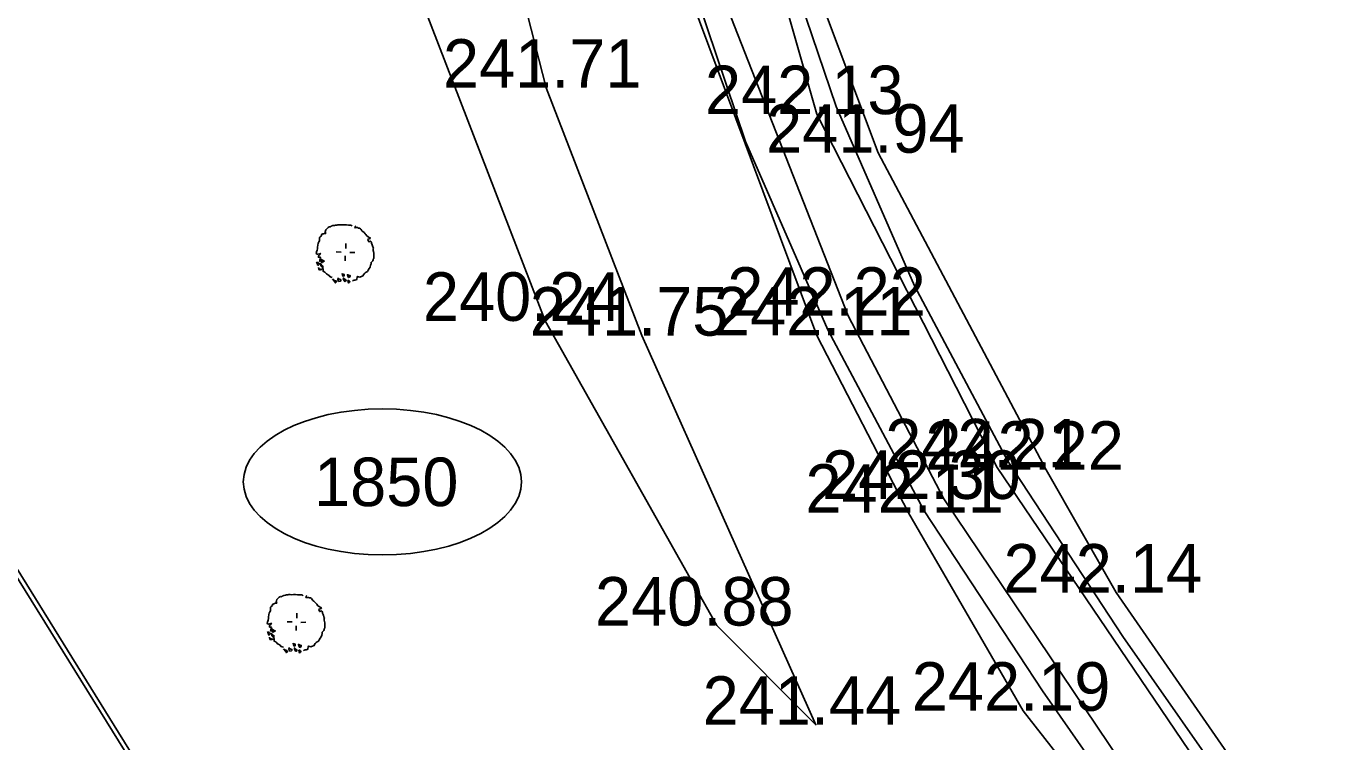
# Model space of a CAD drawing. Extents: x -601754 to -601440, y -1201912 to -1200862.
# Drawn here: x -601535.5 to -601481.8, y -1201665.6 to -1201636.1 of the extents above; entities that cross this region are included whole.
import ezdxf

# ---------------------------------------------------------------- set-up
doc = ezdxf.new("R2010")
doc.units = 0
for name, color, linetype in [('Hranice parcel', 7, 'Continuous'), ('Parcelní čísla', 7, 'Continuous'), ('u_dotčené parcely', 7, 'Continuous'), ('u_hrany', 7, 'Continuous'), ('u_vysadba', 7, 'Continuous'), ('u_vyska', 7, 'Continuous')]:
    doc.layers.add(name, color=color, linetype=linetype)

msp = doc.modelspace()

# ---------------------------------------------------------------- linework, layer by layer
at = {"layer": 'Hranice parcel'}
for points in [[(-601518.5, -1201574.62), (-601510.22, -1201581.07), (-601510.94, -1201612.53), (-601510.72, -1201619.53), (-601510.05, -1201624.75), (-601508.24, -1201633.75), (-601505.86, -1201640.82), (-601502.47, -1201648.58), (-601498.5, -1201656.04), (-601493.62, -1201663.46), (-601488.75, -1201670.45), (-601479.72, -1201682.69), (-601461.88, -1201705.09), (-601454.585, -1201713.629)], [(-601482.011, -1201718.681), (-601492.39, -1201715.61), (-601519.73, -1201684.8), (-601540.64, -1201651.14), (-601563.05, -1201608.38), (-601567.44, -1201599.25)], [(-601460.43, -1201700.48), (-601476.54, -1201680.26), (-601485.5, -1201668.12), (-601490.31, -1201661.22), (-601495.06, -1201653.99), (-601498.9, -1201646.76), (-601502.13, -1201639.37), (-601504.35, -1201632.81), (-601505.66, -1201626.3)]]:
    msp.add_lwpolyline(points, dxfattribs=at)
at = {"layer": 'u_dotčené parcely'}
msp.add_ellipse((-601520.821, -1201654.846), major_axis=(-5.732, 0), ratio=0.524694, dxfattribs=at)
at = {"layer": 'u_hrany'}
for points in [[(-601514.2, -1201569.51), (-601517.03, -1201570.93), (-601522.49, -1201584.67), (-601523.6, -1201596.8), (-601523.78, -1201607.28), (-601522.35, -1201622.38), (-601520.26, -1201632.29), (-601514.11, -1201648.21), (-601507.05, -1201660.77), (-601502.96, -1201664.86), (-601510.13, -1201648.82), (-601514.08, -1201638.6), (-601517, -1201627.14), (-601517.98, -1201618.06), (-601518.55, -1201594.5), (-601514.93, -1201583.59), (-601509.76, -1201580.82)], [(-601567.51, -1201596.21), (-601562.55, -1201607.8), (-601549.33, -1201634.79), (-601540.29, -1201651.32), (-601519.62, -1201684.67)], [(-601460.33, -1201700.35), (-601477.02, -1201679.01), (-601490.59, -1201659.41), (-601493.47, -1201654.35), (-601500.4, -1201641.28), (-601502.56, -1201635.52), (-601504.77, -1201626.02), (-601500.77, -1201618.77)], [(-601454.585, -1201708.29), (-601460.41, -1201701.5), (-601476.94, -1201680.56), (-601485.91, -1201668.41), (-601495.49, -1201654.25), (-601502.92, -1201639.69), (-601504.84, -1201632.93)], [(-601502.92, -1201648.81), (-601508.49, -1201633.89)], [(-601507.17, -1201633.88), (-601501.63, -1201648), (-601497.69, -1201655.55), (-601488, -1201669.96), (-601478.86, -1201682.08), (-601462.72, -1201703.16), (-601454.585, -1201712.627)], [(-601502.92, -1201648.81), (-601499.15, -1201656.12), (-601494.42, -1201664.28), (-601479.96, -1201682.77)]]:
    msp.add_lwpolyline(points, dxfattribs=at)
at = {"layer": 'u_vysadba'}
for points in [[(-601523.335, -1201644.685), (-601523.333, -1201644.656), (-601523.273, -1201644.63), (-601523.243, -1201644.617), (-601523.213, -1201644.604), (-601523.184, -1201644.605), (-601523.155, -1201644.607), (-601523.168, -1201644.577), (-601523.181, -1201644.547), (-601523.164, -1201644.504), (-601523.147, -1201644.461), (-601523.116, -1201644.418), (-601523.085, -1201644.391), (-601523.054, -1201644.363), (-601523.009, -1201644.336), (-601522.965, -1201644.338), (-601522.934, -1201644.311), (-601522.86, -1201644.285), (-601522.801, -1201644.274), (-601522.756, -1201644.262), (-601522.698, -1201644.265), (-601522.653, -1201644.252), (-601522.609, -1201644.255), (-601522.536, -1201644.259), (-601522.463, -1201644.248), (-601522.39, -1201644.252), (-601522.302, -1201644.256), (-601522.214, -1201644.261), (-601522.141, -1201644.265), (-601522.098, -1201644.282), (-601522.07, -1201644.298)], [(-601521.923, -1201644.291), (-601521.939, -1201644.319), (-601521.941, -1201644.349), (-601521.957, -1201644.377), (-601521.912, -1201644.365), (-601521.883, -1201644.366), (-601521.854, -1201644.368), (-601521.811, -1201644.385), (-601521.767, -1201644.387), (-601521.725, -1201644.419), (-601521.697, -1201644.449), (-601521.67, -1201644.495), (-601521.628, -1201644.526), (-601521.572, -1201644.573), (-601521.53, -1201644.619), (-601521.503, -1201644.65), (-601521.462, -1201644.711), (-601521.405, -1201644.743), (-601521.363, -1201644.775), (-601521.32, -1201644.791), (-601521.321, -1201644.821)], [(-601523.335, -1201644.685), (-601523.336, -1201644.7), (-601523.382, -1201644.741), (-601523.413, -1201644.769), (-601523.415, -1201644.813), (-601523.417, -1201644.856), (-601523.42, -1201644.915), (-601523.437, -1201644.958), (-601523.453, -1201644.986), (-601523.469, -1201645.015), (-601523.487, -1201645.072), (-601523.489, -1201645.102), (-601523.492, -1201645.16), (-601523.494, -1201645.204), (-601523.496, -1201645.233), (-601523.514, -1201645.305), (-601523.531, -1201645.348), (-601523.533, -1201645.392), (-601523.549, -1201645.42), (-601523.536, -1201645.45), (-601523.493, -1201645.467), (-601523.404, -1201645.443), (-601523.374, -1201645.43), (-601523.407, -1201645.487), (-601523.437, -1201645.514), (-601523.453, -1201645.543), (-601523.456, -1201645.586), (-601523.427, -1201645.588), (-601523.383, -1201645.59), (-601523.37, -1201645.62), (-601523.387, -1201645.663), (-601523.403, -1201645.692), (-601523.405, -1201645.736), (-601523.407, -1201645.779)], [(-601521.321, -1201644.821), (-601521.366, -1201644.833), (-601521.411, -1201644.845), (-601521.427, -1201644.874), (-601521.414, -1201644.904), (-601521.387, -1201644.949), (-601521.357, -1201644.936), (-601521.312, -1201644.924), (-601521.284, -1201644.954), (-601521.271, -1201644.984), (-601521.273, -1201645.014), (-601521.247, -1201645.074), (-601521.235, -1201645.118), (-601521.222, -1201645.163), (-601521.195, -1201645.208), (-601521.197, -1201645.237), (-601521.199, -1201645.281), (-601521.201, -1201645.31), (-601521.189, -1201645.355), (-601521.177, -1201645.414), (-601521.18, -1201645.472), (-601521.169, -1201645.532), (-601521.17, -1201645.561), (-601521.172, -1201645.59), (-601521.174, -1201645.634), (-601521.205, -1201645.661), (-601521.206, -1201645.691), (-601521.223, -1201645.734), (-601521.239, -1201645.762), (-601521.285, -1201645.804), (-601521.289, -1201645.862), (-601521.306, -1201645.92), (-601521.325, -1201645.992), (-601521.372, -1201646.048), (-601521.405, -1201646.119), (-601521.437, -1201646.176), (-601521.497, -1201646.202), (-601521.528, -1201646.23), (-601521.574, -1201646.272), (-601521.605, -1201646.314), (-601521.622, -1201646.357), (-601521.682, -1201646.383), (-601521.727, -1201646.395), (-601521.757, -1201646.408), (-601521.8, -1201646.391), (-601521.843, -1201646.375), (-601521.86, -1201646.418), (-601521.877, -1201646.475), (-601521.894, -1201646.518), (-601521.939, -1201646.531), (-601521.983, -1201646.528)], [(-601522.519, -1201645.378), (-601522.724, -1201645.367)], [(-601522.335, -1201645.227), (-601522.325, -1201645.022)], [(-601522.169, -1201645.396), (-601521.963, -1201645.393)], [(-601523.539, -1201645.772), (-601523.526, -1201645.802), (-601523.513, -1201645.847), (-601523.5, -1201645.877), (-601523.502, -1201645.906), (-601523.473, -1201645.922), (-601523.443, -1201645.895), (-601523.397, -1201645.853), (-601523.426, -1201645.852), (-601523.468, -1201645.82), (-601523.511, -1201645.803)], [(-601523.449, -1201646.011), (-601523.439, -1201646.1), (-601523.395, -1201646.102), (-601523.366, -1201646.104), (-601523.321, -1201646.091), (-601523.379, -1201646.074), (-601523.423, -1201646.071), (-601523.436, -1201646.041)], [(-601523.381, -1201645.839), (-601523.34, -1201645.885), (-601523.298, -1201645.932), (-601523.256, -1201645.963)], [(-601523.256, -1201645.963), (-601523.285, -1201645.962), (-601523.314, -1201645.96), (-601523.344, -1201645.958), (-601523.357, -1201645.929), (-601523.355, -1201645.899), (-601523.368, -1201645.869)], [(-601523.357, -1201645.65), (-601523.359, -1201645.694), (-601523.346, -1201645.724), (-601523.334, -1201645.769), (-601523.32, -1201645.799), (-601523.291, -1201645.8), (-601523.275, -1201645.772), (-601523.215, -1201645.746), (-601523.258, -1201645.729), (-601523.287, -1201645.713), (-601523.344, -1201645.68)], [(-601522.885, -1201646.422), (-601522.928, -1201646.405), (-601522.956, -1201646.389), (-601522.986, -1201646.387), (-601523.012, -1201646.342), (-601523.041, -1201646.326), (-601523.083, -1201646.294), (-601523.126, -1201646.277), (-601523.168, -1201646.231), (-601523.195, -1201646.201), (-601523.267, -1201646.168), (-601523.264, -1201646.124), (-601523.262, -1201646.08), (-601523.275, -1201646.05), (-601523.304, -1201646.034), (-601523.272, -1201645.992), (-601523.243, -1201645.993)], [(-601522.352, -1201645.533), (-601522.362, -1201645.738)], [(-601522.873, -1201646.481), (-601522.777, -1201646.603), (-601522.75, -1201646.649), (-601522.719, -1201646.606), (-601522.717, -1201646.577), (-601522.746, -1201646.561), (-601522.789, -1201646.544), (-601522.817, -1201646.528), (-601522.846, -1201646.512)], [(-601522.651, -1201646.434), (-601522.655, -1201646.507), (-601522.643, -1201646.552), (-601522.615, -1201646.583), (-601522.556, -1201646.571), (-601522.525, -1201646.543), (-601522.538, -1201646.514), (-601522.581, -1201646.497), (-601522.624, -1201646.48)], [(-601522.481, -1201646.253), (-601522.47, -1201646.327), (-601522.443, -1201646.372), (-601522.398, -1201646.36), (-601522.397, -1201646.331), (-601522.395, -1201646.301), (-601522.438, -1201646.285), (-601522.467, -1201646.268)], [(-601522.446, -1201646.431), (-601522.362, -1201646.508), (-601522.334, -1201646.524), (-601522.321, -1201646.554), (-601522.352, -1201646.582), (-601522.381, -1201646.58), (-601522.394, -1201646.55), (-601522.421, -1201646.505), (-601522.448, -1201646.474)], [(-601522.278, -1201646.293), (-601522.252, -1201646.353), (-601522.239, -1201646.398), (-601522.212, -1201646.428), (-601522.182, -1201646.415), (-601522.15, -1201646.373), (-601522.149, -1201646.344), (-601522.192, -1201646.341), (-601522.221, -1201646.325), (-601522.249, -1201646.309), (-601522.278, -1201646.308)], [(-601522.247, -1201646.544), (-601522.236, -1201646.617), (-601522.223, -1201646.647), (-601522.193, -1201646.634), (-601522.162, -1201646.592), (-601522.189, -1201646.561), (-601522.218, -1201646.545), (-601522.247, -1201646.544)], [(-601521.983, -1201646.528), (-601522.027, -1201646.541), (-601522.058, -1201646.568)], [(-601525.353, -1201659.926), (-601525.352, -1201659.897), (-601525.292, -1201659.871), (-601525.262, -1201659.858), (-601525.232, -1201659.845), (-601525.203, -1201659.847), (-601525.173, -1201659.848), (-601525.186, -1201659.818), (-601525.199, -1201659.788), (-601525.183, -1201659.745), (-601525.166, -1201659.702), (-601525.134, -1201659.66), (-601525.103, -1201659.632), (-601525.073, -1201659.605), (-601525.027, -1201659.578), (-601524.983, -1201659.58), (-601524.953, -1201659.552), (-601524.878, -1201659.527), (-601524.819, -1201659.515), (-601524.774, -1201659.503), (-601524.716, -1201659.506), (-601524.671, -1201659.494), (-601524.628, -1201659.496), (-601524.555, -1201659.5), (-601524.481, -1201659.489), (-601524.408, -1201659.493), (-601524.32, -1201659.498), (-601524.233, -1201659.502), (-601524.16, -1201659.506), (-601524.117, -1201659.523), (-601524.088, -1201659.539)], [(-601525.353, -1201659.926), (-601525.354, -1201659.941), (-601525.4, -1201659.983), (-601525.431, -1201660.01), (-601525.433, -1201660.054), (-601525.435, -1201660.098), (-601525.439, -1201660.156), (-601525.455, -1201660.199), (-601525.472, -1201660.228), (-601525.488, -1201660.256), (-601525.505, -1201660.314), (-601525.507, -1201660.343), (-601525.51, -1201660.401), (-601525.512, -1201660.445), (-601525.514, -1201660.474), (-601525.532, -1201660.547), (-601525.549, -1201660.59), (-601525.552, -1201660.633), (-601525.568, -1201660.662), (-601525.555, -1201660.692), (-601525.512, -1201660.709), (-601525.422, -1201660.684), (-601525.393, -1201660.671), (-601525.425, -1201660.728), (-601525.456, -1201660.756), (-601525.472, -1201660.784), (-601525.474, -1201660.828), (-601525.445, -1201660.829), (-601525.401, -1201660.832), (-601525.388, -1201660.862), (-601525.405, -1201660.905), (-601525.421, -1201660.933), (-601525.423, -1201660.977), (-601525.426, -1201661.021)], [(-601523.941, -1201659.532), (-601523.957, -1201659.561), (-601523.959, -1201659.59), (-601523.975, -1201659.619), (-601523.931, -1201659.606), (-601523.901, -1201659.608), (-601523.872, -1201659.609), (-601523.829, -1201659.626), (-601523.785, -1201659.629), (-601523.743, -1201659.66), (-601523.715, -1201659.691), (-601523.688, -1201659.736), (-601523.646, -1201659.768), (-601523.59, -1201659.815), (-601523.549, -1201659.861), (-601523.521, -1201659.891), (-601523.48, -1201659.952), (-601523.423, -1201659.984), (-601523.381, -1201660.016), (-601523.338, -1201660.033), (-601523.34, -1201660.062)], [(-601524.354, -1201660.468), (-601524.343, -1201660.264)], [(-601523.34, -1201660.062), (-601523.384, -1201660.074), (-601523.429, -1201660.087), (-601523.445, -1201660.115), (-601523.432, -1201660.145), (-601523.405, -1201660.19), (-601523.375, -1201660.177), (-601523.33, -1201660.165), (-601523.303, -1201660.196), (-601523.29, -1201660.226), (-601523.291, -1201660.255), (-601523.265, -1201660.315), (-601523.253, -1201660.36), (-601523.241, -1201660.404), (-601523.214, -1201660.449), (-601523.215, -1201660.479), (-601523.218, -1201660.522), (-601523.219, -1201660.552), (-601523.207, -1201660.596), (-601523.195, -1201660.655), (-601523.198, -1201660.714), (-601523.187, -1201660.773), (-601523.188, -1201660.802), (-601523.19, -1201660.831), (-601523.192, -1201660.875), (-601523.223, -1201660.903), (-601523.225, -1201660.932), (-601523.241, -1201660.975), (-601523.258, -1201661.004), (-601523.304, -1201661.045), (-601523.307, -1201661.103), (-601523.324, -1201661.161), (-601523.343, -1201661.233), (-601523.39, -1201661.289), (-601523.423, -1201661.361), (-601523.455, -1201661.418), (-601523.515, -1201661.444), (-601523.546, -1201661.472), (-601523.592, -1201661.513), (-601523.624, -1201661.555), (-601523.64, -1201661.598), (-601523.7, -1201661.624), (-601523.745, -1201661.637), (-601523.775, -1201661.65), (-601523.818, -1201661.633), (-601523.861, -1201661.616), (-601523.878, -1201661.659), (-601523.896, -1201661.717), (-601523.913, -1201661.76), (-601523.957, -1201661.772), (-601524.001, -1201661.77)], [(-601525.557, -1201661.014), (-601525.544, -1201661.044), (-601525.532, -1201661.088), (-601525.519, -1201661.118), (-601525.52, -1201661.148), (-601525.492, -1201661.164), (-601525.461, -1201661.136), (-601525.415, -1201661.095), (-601525.444, -1201661.093), (-601525.486, -1201661.062), (-601525.529, -1201661.045)], [(-601525.4, -1201661.081), (-601525.358, -1201661.127), (-601525.317, -1201661.173), (-601525.274, -1201661.205)], [(-601525.375, -1201660.892), (-601525.377, -1201660.936), (-601525.364, -1201660.966), (-601525.352, -1201661.01), (-601525.339, -1201661.04), (-601525.31, -1201661.042), (-601525.293, -1201661.013), (-601525.233, -1201660.987), (-601525.277, -1201660.97), (-601525.305, -1201660.954), (-601525.362, -1201660.922)], [(-601524.537, -1201660.619), (-601524.742, -1201660.609)], [(-601524.37, -1201660.775), (-601524.381, -1201660.979)], [(-601524.187, -1201660.638), (-601523.982, -1201660.634)], [(-601525.467, -1201661.253), (-601525.457, -1201661.341), (-601525.413, -1201661.344), (-601525.384, -1201661.345), (-601525.34, -1201661.333), (-601525.397, -1201661.315), (-601525.441, -1201661.313), (-601525.454, -1201661.283)], [(-601525.274, -1201661.205), (-601525.303, -1201661.203), (-601525.333, -1201661.201), (-601525.362, -1201661.2), (-601525.375, -1201661.17), (-601525.373, -1201661.141), (-601525.386, -1201661.111)], [(-601524.903, -1201661.663), (-601524.946, -1201661.647), (-601524.975, -1201661.63), (-601525.004, -1201661.629), (-601525.031, -1201661.583), (-601525.059, -1201661.567), (-601525.101, -1201661.536), (-601525.144, -1201661.519), (-601525.186, -1201661.473), (-601525.214, -1201661.442), (-601525.285, -1201661.409), (-601525.283, -1201661.365), (-601525.28, -1201661.321), (-601525.293, -1201661.291), (-601525.322, -1201661.275), (-601525.29, -1201661.233), (-601525.261, -1201661.235)], [(-601524.499, -1201661.494), (-601524.488, -1201661.568), (-601524.461, -1201661.614), (-601524.417, -1201661.601), (-601524.415, -1201661.572), (-601524.414, -1201661.543), (-601524.457, -1201661.526), (-601524.485, -1201661.51)], [(-601524.296, -1201661.534), (-601524.27, -1201661.594), (-601524.258, -1201661.639), (-601524.23, -1201661.67), (-601524.2, -1201661.657), (-601524.168, -1201661.614), (-601524.167, -1201661.585), (-601524.211, -1201661.583), (-601524.239, -1201661.567), (-601524.268, -1201661.551), (-601524.297, -1201661.549)], [(-601524.892, -1201661.723), (-601524.796, -1201661.845), (-601524.769, -1201661.89), (-601524.737, -1201661.848), (-601524.736, -1201661.819), (-601524.764, -1201661.803), (-601524.807, -1201661.786), (-601524.836, -1201661.769), (-601524.864, -1201661.753)], [(-601524.67, -1201661.676), (-601524.673, -1201661.749), (-601524.661, -1201661.793), (-601524.633, -1201661.824), (-601524.574, -1201661.813), (-601524.544, -1201661.785), (-601524.557, -1201661.755), (-601524.6, -1201661.738), (-601524.643, -1201661.721)], [(-601524.464, -1201661.672), (-601524.381, -1201661.75), (-601524.352, -1201661.766), (-601524.339, -1201661.796), (-601524.37, -1201661.823), (-601524.399, -1201661.822), (-601524.412, -1201661.792), (-601524.439, -1201661.747), (-601524.467, -1201661.716)], [(-601524.265, -1201661.785), (-601524.255, -1201661.859), (-601524.241, -1201661.889), (-601524.212, -1201661.876), (-601524.18, -1201661.833), (-601524.208, -1201661.803), (-601524.236, -1201661.787), (-601524.265, -1201661.785)], [(-601524.001, -1201661.77), (-601524.046, -1201661.782), (-601524.076, -1201661.81)]]:
    msp.add_lwpolyline(points, dxfattribs=at)

# ---------------------------------------------------------------- texts
at = {"layer": 'Parcelní čísla'}
msp.add_text('1850', height=2, dxfattribs=at).set_placement((-601523.64, -1201655.846))
at = {"layer": 'u_vyska'}
for s, p in [('241.71', (-601518.328, -1201638.6)), ('242.13', (-601507.533, -1201639.69)), ('241.94', (-601505.016, -1201641.28)), ('242.22', (-601506.614, -1201648)), ('240.24', (-601519.153, -1201648.21)), ('241.75', (-601514.748, -1201648.82)), ('242.11', (-601507.164, -1201648.81)), ('242.21', (-601500.105, -1201654.25)), ('242.22', (-601498.454, -1201654.35)), ('242.30', (-601502.705, -1201655.55)), ('242.11', (-601503.394, -1201656.12)), ('242.14', (-601495.231, -1201659.41)), ('240.88', (-601512.065, -1201660.77)), ('242.19', (-601499.009, -1201664.28)), ('241.44', (-601507.629, -1201664.86))]:
    msp.add_text(s, height=2, dxfattribs=at).set_placement(p)

doc.saveas('drawing.dxf')
